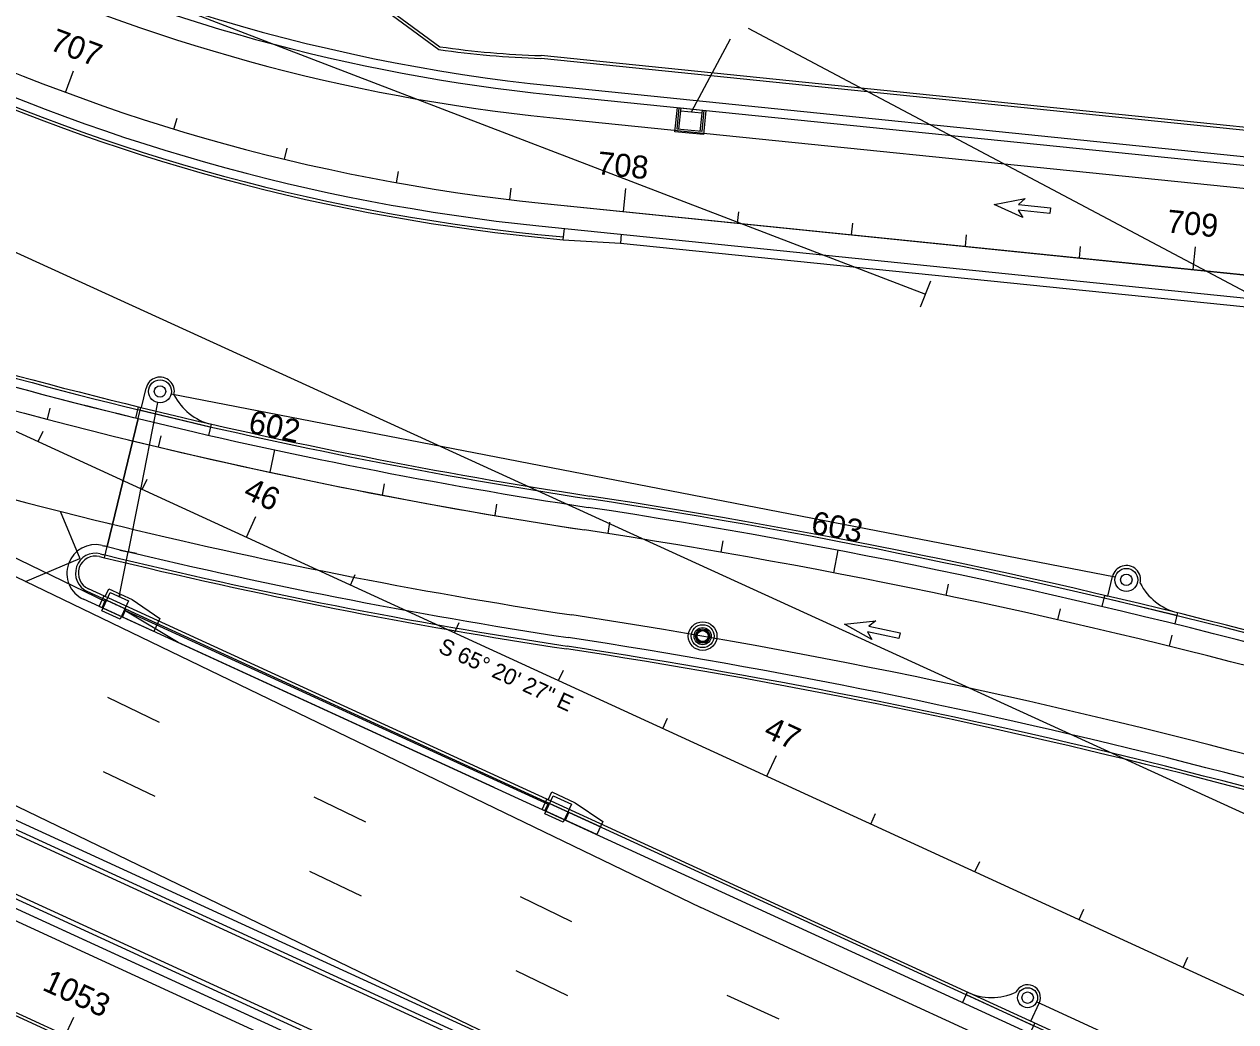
# Model space of a CAD drawing. Extents: x 468143 to 491361, y 1438528 to 1468730.
# Drawn here: x 487597.7 to 487809.2, y 1467199.7 to 1467373.9 of the extents above; entities that cross this region are included whole.
import ezdxf

# ---------------------------------------------------------------- set-up
doc = ezdxf.new("R2010")
doc.units = 0
doc.layers.add('Default', color=7, linetype='Continuous')
doc.layers.add('Xreference_dp', color=7, linetype='Continuous')

# ---------------------------------------------------------------- blocks, each defined once
blk = doc.blocks.new('POINT_DISPLAY')
at = {"layer": 'Default'}
blk.add_line((0, 0), (0, 0), dxfattribs=at)
blk = doc.blocks.new('InltCurb1_35')
at = {"layer": 'Default'}
for p, q in [((2.25, 2), (2.25, 5.5)), ((-10, 2), (-10, 0)), ((-10, 1.5), (3, 1.5)), ((3, 2), (2.25, 2)), ((3, 0), (3, 2))]:
    blk.add_line(p, q, dxfattribs=at)
for radius in [1.75, 1]:
    blk.add_circle((0, 5.5), radius, dxfattribs=at)
for centre, radius, start, end in [((0, 5.5), 2.25, 0, 180), ((-9.85, 12), 10, 269.1432, 319.4677)]:
    blk.add_arc(centre, radius, start, end, dxfattribs=at)
for p in [(-1.22, 6.76), (-0.66, 7.12), (0, 7.75), (0, 7.25), (0, 7.25), (0.7, 7.1), (1.26, 6.72), (-1.75, 5.5), (-1.75, 5.5), (-1.62, 4.84), (-1.6, 6.2), (-1.26, 4.28), (0, 5.5), (0, 5.5), (1.22, 4.24), (1.6, 4.8), (1.62, 6.16), (1.75, 5.5), (1.75, 5.5), (-0.7, 3.9), (0, 3.75), (0, 3.75), (0.66, 3.88), (0, 0), (0, 0)]:
    blk.add_blockref('POINT_DISPLAY', p, dxfattribs=at)
blk = doc.blocks.new('InltCurb5')
at = {"layer": 'Default'}
for p, q in [((-2.25, 3.5), (-8, 2.5)), ((-8, 2.5), (-8, 0)), ((2.25, 3.5), (-2.25, 3.5)), ((2.25, 2), (2.25, 3.5)), ((-8, 1.5), (2.5, 1.5)), ((-8, 0), (2.5, 0)), ((-1.96, 0), (-1.96, 1.5)), ((1.95, 0), (1.95, 1.5)), ((2.5, 2), (2.25, 2)), ((2.5, 0), (2.5, 2))]:
    blk.add_line(p, q, dxfattribs=at)
blk.add_lwpolyline([(-1.75, -0.5), (1.75, -0.5), (1.75, 3), (-1.75, 3)], close=True, dxfattribs=at)
for p in [(-1.75, 3), (0, 3.5), (0, 3), (0, 3), (1.75, 3), (-1.75, 1.25), (-1.75, 1.25), (0, 1.25), (0, 1.25), (1.75, 1.25), (1.75, 1.25), (-1.75, -0.5), (0, 0), (0, 0), (0, -0.5), (0, -0.5), (1.75, -0.5)]:
    blk.add_blockref('POINT_DISPLAY', p, dxfattribs=at)
blk = doc.blocks.new('PBottom40Dia')
at = {"layer": 'Default'}
for radius in [2.5, 2, 2]:
    blk.add_circle((0, 0), radius, dxfattribs=at)
for p in [(-2, 0), (-2, 0), (-1.83, 0.81), (-1.39, 1.43), (-0.75, 1.85), (0, 2), (0, 2), (0, 2), (0, 0), (0, 0), (0.81, 1.83), (1.43, 1.39), (1.85, 0.75), (2, 0), (2, 0), (-1.85, -0.75), (-1.43, -1.39), (-0.81, -1.83), (0, -2), (0, -2), (0, -2), (0.75, -1.85), (1.39, -1.43), (1.83, -0.81)]:
    blk.add_blockref('POINT_DISPLAY', p, dxfattribs=at)
blk = doc.blocks.new('DAMerge_2')
at = {"layer": 'Default'}
blk.add_lwpolyline([(0.71, -4.09), (0, -3.39), (3.95, 0.56), (2.42, 0.68), (7.31, 3.21), (4.77, -1.68), (4.66, -0.15), (0.71, -4.09)], dxfattribs=at)
blk = doc.blocks.new('DAMerge_6')
at = {"layer": 'Default'}
blk.add_lwpolyline([(0.71, -4.09), (0, -3.39), (3.95, 0.56), (2.42, 0.68), (7.31, 3.21), (4.77, -1.68), (4.66, -0.15), (0.71, -4.09)], dxfattribs=at)

msp = doc.modelspace()

# ---------------------------------------------------------------- linework, layer by layer
at = {"layer": 'Xreference_dp'}
for p, q in [((487477.3, 1467433.31), (487755.04, 1467326.77)), ((487372.29, 1467405.61), (488386.67, 1466939.92)), ((487714.17, 1467358.6), (487721.01, 1467371.34)), ((487854.54, 1467304.01), (487724.13, 1467373.15)), ((487846.39, 1467219.77), (487525.36, 1467366.39)), ((487604.86, 1467362), (487606.25, 1467365.75)), ((487690.01, 1467363.12), (487918.82, 1467339.77)), ((487689.85, 1467361.58), (487918.66, 1467338.23)), ((487711.3, 1467355.12), (487711.73, 1467359.35)), ((487711.68, 1467355.59), (487712.06, 1467359.32)), ((487711.73, 1467359.35), (487716.7, 1467358.84)), ((487712.01, 1467355.55), (487712.39, 1467359.28)), ((487712.34, 1467358.79), (487715.99, 1467358.41)), ((487716.04, 1467358.91), (487715.66, 1467355.18)), ((487716.37, 1467358.88), (487715.99, 1467355.15)), ((487716.7, 1467358.84), (487716.27, 1467354.62)), ((487623.81, 1467355.6), (487624.39, 1467357.52)), ((487689.45, 1467357.6), (487917.89, 1467334.29)), ((487716.27, 1467354.62), (487711.3, 1467355.12)), ((487715.99, 1467355.15), (487711.68, 1467355.59)), ((487643.1, 1467350.34), (487643.57, 1467352.28)), ((487662.67, 1467346.23), (487663.02, 1467348.2)), ((487682.45, 1467343.29), (487682.68, 1467345.27)), ((487702.34, 1467341.21), (487702.75, 1467345.19)), ((487687.92, 1467342.68), (487916.74, 1467319.33)), ((487687.92, 1467342.68), (487885.83, 1467322.49)), ((487687.92, 1467342.68), (487881.55, 1467322.92)), ((487722.24, 1467339.18), (487722.44, 1467341.17)), ((487687.52, 1467338.7), (487885.42, 1467318.51)), ((487691.8, 1467336.26), (487692, 1467338.25)), ((487742.13, 1467337.15), (487742.34, 1467339.14)), ((487687.31, 1467336.71), (487691.8, 1467336.26)), ((487687.37, 1467337.21), (487691.85, 1467336.75)), ((487691.8, 1467336.26), (487701.78, 1467335.7)), ((487701.89, 1467337.24), (487701.78, 1467335.7)), ((487701.78, 1467335.7), (487885.23, 1467316.98)), ((487762.03, 1467335.12), (487762.23, 1467337.11)), ((487781.93, 1467333.09), (487782.13, 1467335.08)), ((487801.82, 1467331.06), (487802.23, 1467335.04)), ((487489.67, 1467332.21), (487611.95, 1467273.08)), ((487755.96, 1467329.06), (487754.13, 1467324.47)), ((487518.46, 1467314.99), (487606.04, 1467272.69)), ((487618.13, 1467306.97), (487618.95, 1467310.37)), ((487620.91, 1467307.84), (487617.59, 1467290.89)), ((487788.18, 1467277.35), (487623.32, 1467309.32)), ((487601.7, 1467304.92), (487602.21, 1467306.86)), ((487617.18, 1467305.14), (487617.64, 1467307.08)), ((487630.17, 1467303.56), (487617.53, 1467306.6)), ((487617.57, 1467305.05), (487618.04, 1467306.99)), ((487617.57, 1467305.05), (487618.04, 1467306.99)), ((487617.64, 1467307.08), (487618.13, 1467306.97)), ((487612.13, 1467282.7), (487617.57, 1467305.05)), ((487617.57, 1467305.05), (487612.13, 1467282.7)), ((487630.28, 1467304.05), (487629.82, 1467302.1)), ((487600.1, 1467301.02), (487600.94, 1467302.84)), ((487621.1, 1467300.08), (487621.57, 1467302.03)), ((487640.61, 1467295.67), (487641.45, 1467299.58)), ((487618.28, 1467292.68), (487619.11, 1467294.5)), ((487660.21, 1467291.68), (487660.59, 1467293.64)), ((487617.59, 1467290.89), (487615.81, 1467281.79)), ((487603.92, 1467288.86), (487607.38, 1467280.62)), ((487679.89, 1467288.12), (487680.22, 1467290.09)), ((487897.55, 1467096.74), (487481.23, 1467287.63)), ((487636.46, 1467284.33), (487638.13, 1467287.97)), ((487699.64, 1467284.97), (487699.95, 1467286.94)), ((487896.62, 1467094.69), (487480.46, 1467285.51)), ((487896.93, 1467095.38), (487480.75, 1467286.21)), ((487416.58, 1467283.18), (488348.99, 1466855.64)), ((487892.34, 1467085.38), (487461.6, 1467282.88)), ((487892.66, 1467086.06), (487461.92, 1467283.57)), ((487611.66, 1467280.76), (487612.13, 1467282.7)), ((487611.66, 1467280.76), (487612.13, 1467282.7)), ((487719.37, 1467281.72), (487719.71, 1467283.69)), ((487891.72, 1467084.01), (487460.98, 1467281.52)), ((487597.88, 1467276.63), (487607.38, 1467280.62)), ((487614.27, 1467273.94), (487615.81, 1467281.79)), ((487614.34, 1467282.08), (487615.81, 1467281.79)), ((487617.28, 1467281.5), (487615.81, 1467281.79)), ((487739.05, 1467278.12), (487739.8, 1467282.05)), ((487890.89, 1467082.19), (487460.14, 1467279.7)), ((487654.63, 1467275.99), (487655.47, 1467277.81)), ((487758.66, 1467274.19), (487759.07, 1467276.15)), ((487786.89, 1467274.06), (487787.69, 1467277.46)), ((487520.69, 1467273.94), (487700.82, 1467186.95)), ((487914.85, 1467134.46), (487608.65, 1467274.87)), ((487915.06, 1467134.92), (487608.86, 1467275.32)), ((487614.27, 1467273.94), (487614.26, 1467274.02)), ((487614.27, 1467273.94), (487614.34, 1467273.99)), ((487614.27, 1467273.94), (487614.29, 1467273.98)), ((487614.31, 1467274), (487614.33, 1467274.01)), ((487614.35, 1467274.05), (487614.33, 1467274.11)), ((487614.35, 1467274.16), (487614.36, 1467274.16)), ((487614.38, 1467274.18), (487614.39, 1467274.2)), ((487785.94, 1467272.23), (487786.4, 1467274.17)), ((487786.4, 1467274.17), (487786.89, 1467274.06)), ((487884.84, 1467069.01), (487440.18, 1467272.9)), ((487606.04, 1467272.69), (487715.83, 1467219.67)), ((487914.23, 1467133.1), (487608.02, 1467273.5)), ((487778.19, 1467269.91), (487778.64, 1467271.86)), ((487798.93, 1467270.69), (487786.28, 1467273.69)), ((487689.31, 1467237.61), (487615.13, 1467271.62)), ((487624.53, 1467265.93), (487615.13, 1467271.62)), ((487799.05, 1467271.17), (487798.59, 1467269.23)), ((487672.81, 1467267.64), (487673.64, 1467269.46)), ((487715.14, 1467267.4), (487714.95, 1467267.46)), ((487715.62, 1467267.98), (487715.52, 1467268.16)), ((487715.66, 1467268.01), (487715.57, 1467268.18)), ((487716.42, 1467268.08), (487716.47, 1467268.27)), ((487716.47, 1467268.07), (487716.52, 1467268.26)), ((487717.23, 1467267.68), (487717.05, 1467267.59)), ((487717.25, 1467267.64), (487717.08, 1467267.54)), ((487679.71, 1467240.63), (487624.53, 1467265.93)), ((487715.12, 1467267.35), (487714.93, 1467267.41)), ((487715.2, 1467266.6), (487715.02, 1467266.5)), ((487715.22, 1467266.55), (487715.05, 1467266.46)), ((487715.75, 1467265.88), (487715.81, 1467266.07)), ((487715.8, 1467265.87), (487715.86, 1467266.06)), ((487716.71, 1467265.96), (487716.61, 1467266.13)), ((487716.75, 1467265.98), (487716.66, 1467266.16)), ((487717.33, 1467266.68), (487717.14, 1467266.74)), ((487717.34, 1467266.73), (487717.15, 1467266.79)), ((487797.65, 1467265.29), (487798.13, 1467267.23)), ((487690.98, 1467259.3), (487691.82, 1467261.12)), ((487621.28, 1467252.01), (487612.28, 1467256.36)), ((487709.16, 1467250.96), (487710, 1467252.77)), ((487727.34, 1467242.61), (487729.01, 1467246.25)), ((487620.53, 1467239.05), (487611.53, 1467243.4)), ((487657.3, 1467234.62), (487648.3, 1467238.97)), ((487745.51, 1467234.27), (487746.35, 1467236.08)), ((487639.02, 1467199.88), (487565.95, 1467233.39)), ((487763.69, 1467225.92), (487764.52, 1467227.74)), ((487656.55, 1467221.65), (487647.55, 1467226)), ((487693.32, 1467217.22), (487684.31, 1467221.57)), ((487802.71, 1467179.83), (487715.83, 1467219.67)), ((487781.87, 1467217.58), (487782.7, 1467219.4)), ((487800.04, 1467209.23), (487800.88, 1467211.05)), ((487692.57, 1467204.26), (487683.57, 1467208.61)), ((487729.51, 1467200.19), (487720.42, 1467204.36)), ((487774.49, 1467203.22), (487827.93, 1467178.72)), ((487604.66, 1467196.93), (487606.33, 1467200.57))]:
    msp.add_line(p, q, dxfattribs=at)
for points in [[(487623.93, 1467403.42), (487670.05, 1467369.49)], [(487624.21, 1467403.83), (487670.24, 1467369.96), (487670.24, 1467369.96)], [(487930.7, 1467343.14), (487687.91, 1467367.93)], [(487930.76, 1467343.63), (487930.76, 1467343.63), (487930.76, 1467343.63), (487687.94, 1467368.42)]]:
    msp.add_lwpolyline(points, dxfattribs=at)
for centre, radius in [((487621.38, 1467309.79), 2), ((487621.38, 1467309.79), 1), ((487790.13, 1467276.89), 2), ((487790.13, 1467276.89), 1), ((487716.14, 1467267.07), 1.5), ((487716.14, 1467267.07), 1.25), ((487716.14, 1467267.07), 1.05), ((487716.14, 1467267.07), 1), ((487716.14, 1467267.07), 0.958)]:
    msp.add_circle(centre, radius, dxfattribs=at)
for centre, radius, start, end in [((487722.14, 1467677.97), 318.03, 226.2873, 264.1733), ((487722.14, 1467677.97), 337.03, 223.5592, 264.1733), ((487722.14, 1467677.97), 337.03, 223.5591, 264.1733), ((487722.14, 1467677.97), 322.03, 226.2873, 264.1733), ((487722.14, 1467677.97), 341.03, 224.4359, 264.1733), ((487722.14, 1467677.97), 343.03, 224.4359, 264.1733), ((487722.14, 1467677.97), 342.53, 224.4359, 264.1733), ((487722.14, 1467677.97), 316.49, 241.1368, 264.1733), ((487692.74, 1467526.1), 158.25, 261.7542, 268.2501), ((487692.74, 1467526.1), 157.75, 261.7997, 268.2565), ((487833.29, 1468191.92), 916.73, 245.36712, 261.35759), ((487833.29, 1468191.92), 911.23, 250.72144, 256.32908), ((487833.29, 1468191.92), 910.73, 250.72144, 256.32911), ((487833.29, 1468191.92), 912.73, 250.72144, 256.32899), ((487833.29, 1468191.92), 912.73, 250.72144, 256.27613), ((487833.29, 1468191.92), 931.73, 250.25095, 256.32899), ((487621.38, 1467309.79), 2.5, 346.4921, 166.4921), ((487632.72, 1467313.75), 10, 207.03, 255.9205), ((487833.29, 1468191.92), 911.23, 256.32911, 261.35759), ((487833.29, 1468191.92), 910.73, 256.32911, 261.35759), ((487833.29, 1468191.92), 912.73, 256.32899, 261.35759), ((487833.29, 1468191.92), 916.73, 256.27613, 261.35759), ((487523.34, 1466152.69), 1151.42, 68.89997, 81.35759), ((487523.34, 1466152.69), 1151.92, 68.89997, 81.35759), ((487523.34, 1466152.69), 1149.92, 68.1961, 81.35759), ((487833.29, 1468191.92), 931.73, 256.27613, 261.35759), ((487523.34, 1466152.69), 1145.92, 68.1961, 81.35759), ((487523.34, 1466152.69), 1145.92, 68.1961, 81.35759), ((487610.11, 1467278.05), 5, 76.2756, 245.3671), ((487827.83, 1468169.58), 912.73, 256.27612, 256.33033), ((487833.29, 1468191.92), 935.73, 256.32899, 261.35759), ((487610.11, 1467278.05), 3.5, 76.2756, 245.3671), ((487610.11, 1467278.05), 3, 76.2756, 245.3671), ((487827.02, 1468166.17), 911.23, 256.27479, 256.32908), ((487827.14, 1468166.66), 911.23, 256.27482, 256.32908), ((487833.29, 1468191.92), 937.73, 256.32888, 261.35759), ((487833.29, 1468191.92), 937.23, 256.32888, 261.35759), ((487790.13, 1467276.89), 2.5, 346.65, 166.65), ((487801.45, 1467280.88), 10, 207.1878, 256.0783), ((487523.34, 1466152.69), 1130.92, 68.1961, 81.35759), ((487523.34, 1466152.69), 1130.92, 68.1961, 81.35759), ((487523.34, 1466152.69), 1125.42, 70.14933, 81.35759), ((487523.34, 1466152.69), 1126.92, 70.14997, 81.35759), ((487523.34, 1466152.69), 1124.92, 70.14912, 81.35759)]:
    msp.add_arc(centre, radius, start, end, dxfattribs=at)
for centre, major_axis, start_param, end_param in [((487614.36, 1467273.95), (-0.0656, 0.0301), 5.759586, 6.283185), ((487614.4, 1467274.11), (0.0656, -0.0301), 2.617994, 3.665191), ((487614.28, 1467274.05), (-0.0656, 0.0301), 2.617994, 3.665191), ((487614.32, 1467274.21), (0.0656, -0.0301), 5.759586, 6.283185)]:
    msp.add_ellipse(centre, major_axis=major_axis, ratio=0.666667, start_param=start_param, end_param=end_param, dxfattribs=at)

# ---------------------------------------------------------------- block references
for name, p, yscale, rotation in [('POINT_DISPLAY', (487712.34, 1467358.79), -0.9999999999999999, 174.1732697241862), ('POINT_DISPLAY', (487714.17, 1467358.6), -0.9999999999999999, 174.1732697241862), ('POINT_DISPLAY', (487714.17, 1467358.6), -0.9999999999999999, 174.1732697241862), ('POINT_DISPLAY', (487714.22, 1467359.1), -0.9999999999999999, 174.1732697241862), ('POINT_DISPLAY', (487714.22, 1467359.1), -0.9999999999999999, 174.1732697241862), ('POINT_DISPLAY', (487715.99, 1467358.41), -0.9999999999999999, 174.1732697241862), ('POINT_DISPLAY', (487712.18, 1467357.17), -0.9999999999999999, 174.1732697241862), ('POINT_DISPLAY', (487712.18, 1467357.17), -0.9999999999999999, 174.1732697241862), ('POINT_DISPLAY', (487714, 1467356.98), -0.9999999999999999, 174.1732697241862), ('POINT_DISPLAY', (487714, 1467356.98), -0.9999999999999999, 174.1732697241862), ('POINT_DISPLAY', (487715.83, 1467356.8), -0.9999999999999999, 174.1732697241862), ('POINT_DISPLAY', (487715.83, 1467356.8), -0.9999999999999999, 174.1732697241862), ('POINT_DISPLAY', (487712.01, 1467355.55), -0.9999999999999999, 174.1732697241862), ('POINT_DISPLAY', (487713.79, 1467354.87), -0.9999999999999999, 174.1732697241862), ('POINT_DISPLAY', (487713.84, 1467355.37), -0.9999999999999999, 174.1732697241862), ('POINT_DISPLAY', (487713.84, 1467355.37), -0.9999999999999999, 174.1732697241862), ('POINT_DISPLAY', (487715.66, 1467355.18), -0.9999999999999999, 174.1732697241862), ('POINT_DISPLAY', (487621.96, 1467312.22), -1.0000000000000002, 166.49211903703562), ('POINT_DISPLAY', (487619.43, 1467310.25), -1.0000000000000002, 166.49211903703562), ('POINT_DISPLAY', (487619.43, 1467310.25), -1.0000000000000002, 166.49211903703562), ('POINT_DISPLAY', (487619.75, 1467310.95), -1.0000000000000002, 166.49211903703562), ('POINT_DISPLAY', (487620.31, 1467311.48), -1.0000000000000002, 166.49211903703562), ('POINT_DISPLAY', (487621.02, 1467311.75), -1.0000000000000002, 166.49211903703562), ('POINT_DISPLAY', (487621.38, 1467309.79), -1.0000000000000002, 166.49211903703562), ('POINT_DISPLAY', (487621.38, 1467309.79), -1.0000000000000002, 166.49211903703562), ('POINT_DISPLAY', (487621.85, 1467311.73), -1.0000000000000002, 166.49211903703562), ('POINT_DISPLAY', (487621.85, 1467311.73), -1.0000000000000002, 166.49211903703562), ('POINT_DISPLAY', (487622.54, 1467311.41), -1.0000000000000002, 166.49211903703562), ('POINT_DISPLAY', (487623.07, 1467310.85), -1.0000000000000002, 166.49211903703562), ('POINT_DISPLAY', (487623.35, 1467310.14), -1.0000000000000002, 166.49211903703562), ('POINT_DISPLAY', (487619.41, 1467309.43), -1.0000000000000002, 166.49211903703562), ('POINT_DISPLAY', (487619.69, 1467308.72), -1.0000000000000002, 166.49211903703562), ('POINT_DISPLAY', (487620.21, 1467308.16), -1.0000000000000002, 166.49211903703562), ('POINT_DISPLAY', (487620.91, 1467307.84), -1.0000000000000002, 166.49211903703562), ('POINT_DISPLAY', (487620.91, 1467307.84), -1.0000000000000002, 166.49211903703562), ('POINT_DISPLAY', (487621.73, 1467307.82), -1.0000000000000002, 166.49211903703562), ('POINT_DISPLAY', (487622.45, 1467308.1), -1.0000000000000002, 166.49211903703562), ('POINT_DISPLAY', (487623.01, 1467308.62), -1.0000000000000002, 166.49211903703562), ('POINT_DISPLAY', (487623.32, 1467309.32), -1.0000000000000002, 166.49211903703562), ('POINT_DISPLAY', (487623.32, 1467309.32), -1.0000000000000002, 166.49211903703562), ('POINT_DISPLAY', (487620.09, 1467304.44), -1.0000000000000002, 166.49211903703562), ('POINT_DISPLAY', (487620.09, 1467304.44), -1.0000000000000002, 166.49211903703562), ('POINT_DISPLAY', (487788.5, 1467278.05), -0.9999999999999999, 166.64996536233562), ('POINT_DISPLAY', (487789.05, 1467278.57), -0.9999999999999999, 166.64996536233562), ('POINT_DISPLAY', (487789.76, 1467278.85), -0.9999999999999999, 166.64996536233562), ('POINT_DISPLAY', (487790.59, 1467278.83), -0.9999999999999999, 166.64996536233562), ('POINT_DISPLAY', (487790.59, 1467278.83), -0.9999999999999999, 166.64996536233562), ('POINT_DISPLAY', (487790.7, 1467279.32), -0.9999999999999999, 166.64996536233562), ('POINT_DISPLAY', (487791.29, 1467278.52), -0.9999999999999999, 166.64996536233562), ('POINT_DISPLAY', (487788.16, 1467276.53), -0.9999999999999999, 166.64996536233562), ('POINT_DISPLAY', (487788.18, 1467277.35), -0.9999999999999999, 166.64996536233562), ('POINT_DISPLAY', (487788.18, 1467277.35), -0.9999999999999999, 166.64996536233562), ('POINT_DISPLAY', (487790.13, 1467276.89), -0.9999999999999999, 166.64996536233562), ('POINT_DISPLAY', (487790.13, 1467276.89), -0.9999999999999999, 166.64996536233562), ('POINT_DISPLAY', (487791.81, 1467277.96), -0.9999999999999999, 166.64996536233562), ('POINT_DISPLAY', (487792.07, 1467276.43), -0.9999999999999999, 166.64996536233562), ('POINT_DISPLAY', (487792.07, 1467276.43), -0.9999999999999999, 166.64996536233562), ('POINT_DISPLAY', (487792.09, 1467277.25), -0.9999999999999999, 166.64996536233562), ('InltCurb5', (487613.02, 1467271.21), -1, 155.3671192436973), ('POINT_DISPLAY', (487788.44, 1467275.81), -0.9999999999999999, 166.64996536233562), ('POINT_DISPLAY', (487788.97, 1467275.26), -0.9999999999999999, 166.64996536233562), ('POINT_DISPLAY', (487789.66, 1467274.94), -0.9999999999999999, 166.64996536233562), ('POINT_DISPLAY', (487789.66, 1467274.94), -0.9999999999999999, 166.64996536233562), ('POINT_DISPLAY', (487790.49, 1467274.92), -0.9999999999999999, 166.64996536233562), ('POINT_DISPLAY', (487791.2, 1467275.2), -0.9999999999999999, 166.64996536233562), ('POINT_DISPLAY', (487791.76, 1467275.73), -0.9999999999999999, 166.64996536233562), ('POINT_DISPLAY', (487788.86, 1467271.54), -0.9999999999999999, 166.64996536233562), ('POINT_DISPLAY', (487788.86, 1467271.54), -0.9999999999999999, 166.64996536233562), ('InltCurb5', (487690.38, 1467235.75), -1, 155.3671192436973)]:
    msp.add_blockref(name, p, dxfattribs=dict(at, yscale=yscale, rotation=rotation))
for name, p, rotation in [('DAMerge_2', (487774.13, 1467338.72), 128.8122042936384), ('DAMerge_6', (487774.13, 1467338.72), 128.8122042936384), ('DAMerge_2', (487747.59, 1467264.81), 123.29886146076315), ('DAMerge_6', (487747.59, 1467264.81), 123.29886146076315), ('PBottom40Dia', (487716.14, 1467267.07), -151.81553463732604), ('POINT_DISPLAY', (487715.43, 1467268.39), -151.81553463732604), ('POINT_DISPLAY', (487715.67, 1467267.95), -151.81553463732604), ('POINT_DISPLAY', (487716.43, 1467268.03), -151.81553463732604), ('POINT_DISPLAY', (487717.02, 1467267.54), -151.81553463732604), ('POINT_DISPLAY', (487715.18, 1467267.36), -151.81553463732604), ('POINT_DISPLAY', (487715.26, 1467266.6), -151.81553463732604), ('POINT_DISPLAY', (487715.85, 1467266.11), -151.81553463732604), ('POINT_DISPLAY', (487716.14, 1467267.07), -151.81553463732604), ('POINT_DISPLAY', (487716.14, 1467267.07), -151.81553463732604), ('POINT_DISPLAY', (487716.14, 1467267.07), -151.81553463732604), ('POINT_DISPLAY', (487716.61, 1467266.19), -151.81553463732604), ('POINT_DISPLAY', (487716.85, 1467265.75), -151.81553463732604), ('POINT_DISPLAY', (487717.1, 1467266.78), -151.81553463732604), ('InltCurb1_35', (487770.6, 1467198.95), -24.632880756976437)]:
    msp.add_blockref(name, p, dxfattribs=dict(at, rotation=rotation))

# ---------------------------------------------------------------- texts
for s, height, rotation, p in [('707', 4, 339.6368, (487601.9, 1467369.5)), ('708', 4, 354.1733, (487697.59, 1467347.73)), ('709', 4, 354.1733, (487797.07, 1467337.57)), ('602', 4, 347.8671, (487636.61, 1467302.66)), ('46', 4, 335.3408, (487635.7, 1467291.28)), ('603', 4, 349.15, (487734.89, 1467285.03)), ('S 65%%d 20\' 27" E', 2.8, 335.3408, (487669.8, 1467264.32)), ('47', 4, 335.3408, (487726.58, 1467249.56)), ('1053', 4, 335.3671, (487600.63, 1467205.38))]:
    msp.add_text(s, height=height, rotation=rotation, dxfattribs=at).set_placement(p)

doc.saveas('drawing.dxf')
